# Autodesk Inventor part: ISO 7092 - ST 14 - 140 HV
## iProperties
IsCustomPart: 0
Created: 2009-02
Part Number: ISO 7092 - ST 14 - 140 HV
Material: Stainless Steel
Description: Plain washers-Small series-Product grade A
Document SubType Name: Modeling
Standard: ISO 7092
Designer: 904Chiaki
Standard Revision: Second edition 2000-06-01
Standards Organization: ISO
Language: en-US
Size Designation: ST 14 - 140 HV
Categories: <MemberInstance><Categories><Category DisplayName="Fasteners" InternalName="e4da775c-781d-43d5-af7c-5136215cf5a6" Mnemonic="FSTN"><Category DisplayName="Washers
Density: 8.08 g/cm^3
Mass: 5.56863 g
Surface Area: 8.57655 cm^2
Volume: 0.689187 cm^3
Author: 904Chiaki
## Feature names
1. Body [Extrusion]
